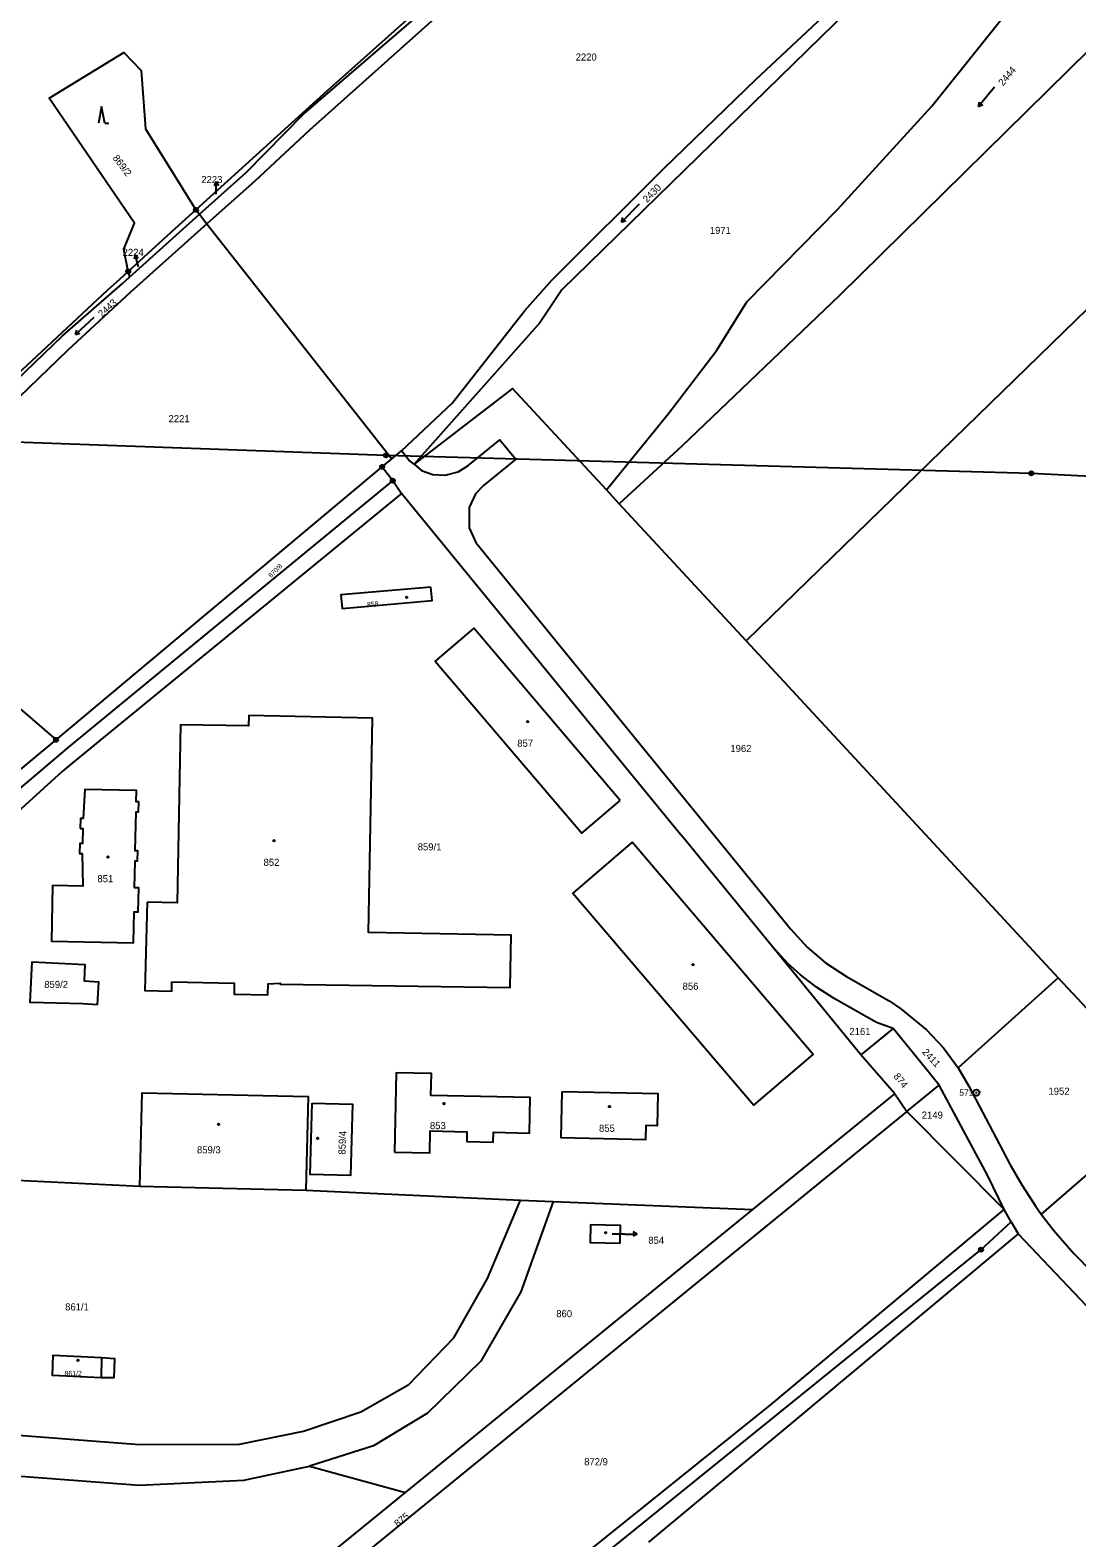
# Model space of a CAD drawing. Extents: x -504988 to -494607, y -1123820 to -1114018.
# Drawn here: x -502606.4 to -502355.4, y -1119993 to -1119631.6 of the extents above; entities that cross this region are included whole.
import ezdxf

# ---------------------------------------------------------------- set-up
doc = ezdxf.new("R2010")
doc.units = 0
for name, color, linetype in [('Hranice parcel', 7, 'Continuous'), ('Parcelní čísla', 7, 'Continuous'), ('Pop  PČ popisy', 7, 'Continuous'), ('Poz předměty', 7, 'Continuous'), ('Vnitřní kresba', 7, 'Continuous'), ('Značky bodu BP', 7, 'Continuous'), ('Značky budov', 7, 'Continuous'), ('Značky kultur', 7, 'Continuous')]:
    doc.layers.add(name, color=color, linetype=linetype)

msp = doc.modelspace()

# ---------------------------------------------------------------- linework, layer by layer
at = {"layer": 'Hranice parcel'}
for p, q in [((-502582.58, -1119690.79), (-502565.8, -1119675.75)), ((-502566.63, -1119674.69), (-502565.8, -1119675.75)), ((-502565.8, -1119675.75), (-502564, -1119678.03)), ((-502564, -1119678.03), (-502519.65, -1119734.37)), ((-502582.88, -1119689.44), (-502582.58, -1119690.79)), ((-502521.98, -1119736.27), (-502519.65, -1119734.37)), ((-502519.65, -1119734.37), (-502517.33, -1119732.48)), ((-502600.2, -1119801.7), (-502521.98, -1119736.27)), ((-502465.11, -1119745.14), (-502468.21, -1119741.8)), ((-502434.66, -1119778), (-502465.11, -1119745.14)), ((-502434.66, -1119778), (-502359.83, -1119858.73)), ((-502608.76, -1119794.28), (-502600.2, -1119801.7)), ((-502612.94, -1119812.35), (-502600.2, -1119801.7)), ((-502407.2, -1119877.25), (-502428.73, -1119850.93)), ((-502359.83, -1119858.73), (-502383.84, -1119880.37)), ((-502345.74, -1119873.93), (-502359.83, -1119858.73)), ((-502399.46, -1119870.92), (-502407.2, -1119877.25)), ((-502399.04, -1119886.56), (-502407.2, -1119877.25)), ((-502396.12, -1119890.8), (-502388.38, -1119884.46)), ((-502433.06, -1119914.26), (-502399.04, -1119886.56)), ((-502399.04, -1119886.56), (-502396.12, -1119890.8)), ((-502334.35, -1119889.76), (-502363.93, -1119915.42)), ((-502372.84, -1119914.3), (-502396.12, -1119890.8)), ((-502580.09, -1119908.69), (-502540.31, -1119909.68)), ((-502540.31, -1119909.68), (-502488.77, -1119912.04)), ((-502516.42, -1119982.14), (-502433.06, -1119914.26)), ((-502488.77, -1119912.04), (-502480.94, -1119912.35)), ((-502480.94, -1119912.35), (-502433.06, -1119914.26)), ((-502371.14, -1119917.24), (-502372.84, -1119914.3)), ((-502371.14, -1119917.24), (-502369.46, -1119920.13)), ((-502369.46, -1119920.13), (-502271.25, -1120023.8)), ((-502539.37, -1119975.81), (-502516.42, -1119982.14))]:
    msp.add_line(p, q, dxfattribs=at)
for points in [[(-502128.78, -1119382.75), (-502164.9, -1119386.2), (-502173.21, -1119390.26), (-502179.16, -1119399.85), (-502187, -1119431.57), (-502190.07, -1119444.01), (-502204.27, -1119473.56), (-502214.16, -1119489.36), (-502223.74, -1119506.4), (-502229.87, -1119513.8), (-502240.15, -1119526.05), (-502265.45, -1119550.93), (-502277.57, -1119560.18), (-502280.74, -1119562.7), (-502299.2, -1119571.51), (-502311.6, -1119583.47), (-502326.57, -1119605.06), (-502347.46, -1119631.46), (-502412.32, -1119695.22), (-502450.15, -1119731.29), (-502465.11, -1119745.14)], [(-502128.78, -1119382.75), (-502147.68, -1119459.24), (-502164.97, -1119495.21), (-502195.47, -1119542.5), (-502236.04, -1119584.84), (-502335.35, -1119681.42), (-502434.66, -1119778)], [(-502517.33, -1119732.48), (-502505.19, -1119721.04), (-502487.78, -1119698.79), (-502481.31, -1119691.51), (-502454.36, -1119664.71), (-502432.4, -1119643.44), (-502407.66, -1119620.25), (-502391.32, -1119604.16), (-502379, -1119591.92), (-502374.38, -1119584.08), (-502377.64, -1119576.05), (-502384.59, -1119563.69), (-502393.33, -1119552.76), (-502401.5, -1119542.45), (-502404.17, -1119542.98), (-502429.48, -1119562.95), (-502464.86, -1119592.04), (-502498.22, -1119618.75), (-502539.44, -1119655.59), (-502552.42, -1119667.72), (-502564, -1119678.03)], [(-502371.1, -1119588.68), (-502478.87, -1119693.82), (-502484.2, -1119701.73), (-502514.33, -1119735.66)], [(-502468.21, -1119741.8), (-502453.32, -1119723.48), (-502441.76, -1119708.31), (-502434.49, -1119696.75), (-502412.82, -1119674.63), (-502390.2, -1119649.83), (-502366.32, -1119620), (-502363.15, -1119610.6), (-502367.08, -1119594.08), (-502371.1, -1119588.68)], [(-502508.12, -1119622.05), (-502535.21, -1119646.18), (-502566.63, -1119674.69)], [(-502565.8, -1119675.75), (-502554.59, -1119665.71), (-502540.73, -1119651.67), (-502507.62, -1119623.08)], [(-502582.88, -1119689.44), (-502583.97, -1119684.1), (-502581.37, -1119677.85), (-502601.85, -1119647.92), (-502583.97, -1119636.95), (-502579.81, -1119641.28), (-502578.77, -1119655.23), (-502566.63, -1119674.69)], [(-502566.63, -1119674.69), (-502571.67, -1119679.26), (-502582.88, -1119689.44)], [(-502564, -1119678.03), (-502582.36, -1119694.39), (-502597.39, -1119708.35), (-502611.46, -1119721.88), (-502617.56, -1119736.16)], [(-502616.8, -1119729.06), (-502612.03, -1119717.7), (-502598.64, -1119704.84), (-502584.29, -1119692.32), (-502582.58, -1119690.79)], [(-502582.88, -1119689.44), (-502584.98, -1119691.35), (-502587.84, -1119693.94), (-502615.83, -1119719.98)], [(-502468.21, -1119741.8), (-502490.76, -1119717.47), (-502514.33, -1119735.66)], [(-502514.33, -1119735.66), (-502512.52, -1119737.15), (-502509.83, -1119738.12), (-502506.88, -1119738.28), (-502503.78, -1119737.48), (-502501.44, -1119736.03), (-502493.75, -1119729.77), (-502489.96, -1119734.42), (-502497.71, -1119740.73), (-502499.57, -1119742.72), (-502501.09, -1119746.01), (-502501.11, -1119750.87), (-502499.48, -1119754.38), (-502424.08, -1119847.02), (-502420.04, -1119851.43), (-502415.64, -1119855.17), (-502410.61, -1119858.46), (-502400.37, -1119864.31), (-502397.56, -1119866.17), (-502391.46, -1119871.2), (-502387.4, -1119875.56), (-502383.84, -1119880.37)], [(-502514.33, -1119735.66), (-502515.57, -1119734.64), (-502517.33, -1119732.48)], [(-502521.98, -1119736.27), (-502519.43, -1119739.59), (-502517.35, -1119742.66)], [(-502517.35, -1119742.66), (-502596.36, -1119807.31), (-502598.74, -1119809.28), (-502621.06, -1119829.53)], [(-502428.73, -1119850.93), (-502449.42, -1119825.64), (-502450.82, -1119823.93), (-502453.39, -1119820.8), (-502513.39, -1119747.48), (-502517.35, -1119742.66)], [(-502510.29, -1119765.08), (-502531.9, -1119766.98), (-502531.61, -1119770.26), (-502510, -1119768.35), (-502510.29, -1119765.08)], [(-502464.87, -1119816.24), (-502499.99, -1119774.98), (-502509.24, -1119782.85), (-502474.12, -1119824.1), (-502464.87, -1119816.24)], [(-502572.4, -1119859.76), (-502557.44, -1119860.04), (-502557.49, -1119862.68), (-502549.37, -1119862.84), (-502549.32, -1119860.23), (-502546.44, -1119860), (-502546.44, -1119860.29), (-502491.27, -1119861.04), (-502491.03, -1119848.55), (-502525.26, -1119847.9), (-502524.29, -1119796.49), (-502553.98, -1119795.92), (-502554.03, -1119798.38), (-502570.32, -1119798.08), (-502571.14, -1119840.77), (-502578.33, -1119840.66)], [(-502594.37, -1119822.97), (-502593.78, -1119822.99), (-502593.87, -1119826.57), (-502594.46, -1119826.55), (-502594.53, -1119828.96), (-502593.94, -1119828.98), (-502593.75, -1119836.77), (-502601.04, -1119836.62), (-502601.31, -1119849.96), (-502581.64, -1119850.36), (-502581.49, -1119842.94), (-502580.53, -1119842.96), (-502580.33, -1119837.19), (-502581.37, -1119837.17), (-502581.24, -1119830.74), (-502580.64, -1119830.75), (-502580.59, -1119828.32), (-502581.19, -1119828.31), (-502580.99, -1119819), (-502580.4, -1119819.01), (-502580.35, -1119816.6), (-502580.95, -1119816.59), (-502580.89, -1119813.89), (-502593.27, -1119813.64), (-502593.72, -1119820.56), (-502594.31, -1119820.54), (-502594.37, -1119822.97)], [(-502462, -1119826.27), (-502476.24, -1119838.43), (-502432.84, -1119889.29), (-502418.59, -1119877.13), (-502462, -1119826.27)], [(-502621.06, -1119829.53), (-502622.79, -1119906.64), (-502580.09, -1119908.69)], [(-502578.33, -1119840.66), (-502578.87, -1119861.77), (-502572.46, -1119861.92), (-502572.4, -1119859.76)], [(-502399.46, -1119870.92), (-502403.4, -1119869.45), (-502413.57, -1119863.68), (-502417.84, -1119860.99), (-502421.65, -1119858.06), (-502424.68, -1119855.29), (-502428.73, -1119850.93)], [(-502590.32, -1119865.2), (-502593.76, -1119865.03), (-502606.37, -1119864.7), (-502605.95, -1119854.92), (-502593.26, -1119855.53), (-502593.45, -1119859.51), (-502590.01, -1119859.69), (-502590.32, -1119865.2)], [(-502388.38, -1119884.46), (-502391.79, -1119880.3), (-502399.46, -1119870.92)], [(-502519.03, -1119900.55), (-502510.57, -1119900.73), (-502510.46, -1119895.47), (-502501.64, -1119895.66), (-502501.7, -1119898.03), (-502495.36, -1119898.17), (-502495.31, -1119895.79), (-502486.68, -1119895.98), (-502486.5, -1119887.46), (-502510.28, -1119886.94), (-502510.16, -1119881.73), (-502518.61, -1119881.54), (-502519.03, -1119900.55)], [(-502383.84, -1119880.37), (-502381.27, -1119884.73), (-502371.42, -1119903.42), (-502368.61, -1119908.39), (-502365.24, -1119913.58), (-502363.93, -1119915.42)], [(-502580.09, -1119908.69), (-502579.57, -1119886.33), (-502539.73, -1119887.19), (-502540.31, -1119909.68)], [(-502478.87, -1119886.1), (-502479.1, -1119897.06), (-502458.74, -1119897.49), (-502458.67, -1119894.08), (-502455.96, -1119894.14), (-502455.8, -1119886.58), (-502478.87, -1119886.1)], [(-502372.84, -1119914.3), (-502376.73, -1119906.22), (-502388.38, -1119884.46)], [(-502538.74, -1119888.77), (-502529.12, -1119889.02), (-502529.58, -1119906.12), (-502539.22, -1119905.9), (-502538.74, -1119888.77)], [(-502396.12, -1119890.8), (-502566.84, -1120029.94), (-502587.36, -1120052.45), (-502608.42, -1120076.47), (-502633.38, -1120096.81)], [(-502701.82, -1119961), (-502680.9, -1119959.47), (-502648.34, -1119962.6), (-502617.61, -1119967.74), (-502580.14, -1119970.61), (-502556.23, -1119970.53), (-502540.81, -1119967.45), (-502527.06, -1119962.76), (-502515.62, -1119956.25), (-502504.82, -1119945.07), (-502496.7, -1119930.81), (-502488.77, -1119912.04)], [(-502539.17, -1120129.38), (-502550.09, -1120101.33), (-502565.41, -1120066.4), (-502556.62, -1120058.59), (-502542.2, -1120052.17), (-502428.59, -1119960.97), (-502372.84, -1119914.3)], [(-502480.94, -1119912.35), (-502488.75, -1119934), (-502498.32, -1119950.65), (-502511.11, -1119963.08), (-502524.08, -1119970.96), (-502539.37, -1119975.81)], [(-502510.03, -1120162.22), (-502522.53, -1120148.04), (-502540.02, -1120119.07), (-502555.09, -1120082.05), (-502553.66, -1120072.7), (-502545.55, -1120063.24), (-502488.39, -1120012.91), (-502378.38, -1119923.93), (-502371.14, -1119917.24)], [(-502464.91, -1119922.34), (-502464.82, -1119918.15), (-502471.99, -1119918), (-502472.07, -1119922.19), (-502464.91, -1119922.34)], [(-502363.93, -1119915.42), (-502360.92, -1119919.32), (-502356.11, -1119924.82), (-502271.75, -1120010.63), (-502258.23, -1120024.92), (-502255.98, -1120027.81), (-502253.76, -1120034.16), (-502254.99, -1120043.43), (-502256.73, -1120046.58), (-502346.48, -1120124.79), (-502436.23, -1120202.99)], [(-502369.46, -1119920.13), (-502423.33, -1119965.12), (-502458.12, -1119994.04)], [(-502589.31, -1119949.73), (-502586.18, -1119950.02), (-502586.33, -1119954.61), (-502589.36, -1119954.61), (-502601.08, -1119954.06), (-502600.85, -1119949.2), (-502589.31, -1119949.73)], [(-502701.9, -1119970.8), (-502681.57, -1119972.49), (-502648.5, -1119972.28), (-502619.23, -1119977.45), (-502580.24, -1119980.39), (-502555.18, -1119979.17), (-502539.37, -1119975.81)], [(-502591.59, -1120050.18), (-502570.78, -1120026.41), (-502516.42, -1119982.14)]]:
    msp.add_lwpolyline(points, dxfattribs=at)
at = {"layer": 'Pop  PČ popisy'}
for p, q in [((-502561.76, -1119667.9), (-502562.26, -1119668.9)), ((-502561.76, -1119670.9), (-502561.76, -1119667.9)), ((-502561.76, -1119667.9), (-502561.26, -1119668.9)), ((-502581.23, -1119685.4), (-502581.45, -1119686.5)), ((-502580.45, -1119688.3), (-502581.23, -1119685.4)), ((-502581.23, -1119685.4), (-502580.48, -1119686.24)), ((-502463.8, -1119920.17), (-502466.8, -1119920.17)), ((-502463.8, -1119920.17), (-502460.8, -1119920.17)), ((-502460.8, -1119920.17), (-502461.8, -1119919.67)), ((-502460.8, -1119920.17), (-502461.8, -1119920.67))]:
    msp.add_line(p, q, dxfattribs=at)
at = {"layer": 'Poz předměty'}
for p, q in [((-502656.18, -1119728.63), (-502521.05, -1119733.51)), ((-502521.05, -1119733.51), (-502366.32, -1119737.83)), ((-502366.32, -1119737.83), (-502184.57, -1119746.9))]:
    msp.add_line(p, q, dxfattribs=at)
for centre, radius in [((-502521.05, -1119733.51), 0.5), ((-502521.05, -1119733.51), 0.4), ((-502521.05, -1119733.51), 0.3), ((-502521.05, -1119733.51), 0.2), ((-502521.05, -1119733.51), 0.1), ((-502366.32, -1119737.83), 0.5), ((-502366.32, -1119737.83), 0.4), ((-502366.32, -1119737.83), 0.3), ((-502366.32, -1119737.83), 0.2), ((-502366.32, -1119737.83), 0.1)]:
    msp.add_circle(centre, radius, dxfattribs=at)
at = {"layer": 'Vnitřní kresba'}
for p, q in [((-502519.43, -1119739.59), (-502597.5, -1119803.74)), ((-502597.5, -1119803.74), (-502632.3, -1119833.14)), ((-502589.31, -1119949.73), (-502589.36, -1119954.61))]:
    msp.add_line(p, q, dxfattribs=at)
at = {"layer": 'Značky bodu BP'}
for centre, radius in [((-502566.63, -1119674.69), 0.5), ((-502566.63, -1119674.69), 0.0303), ((-502582.88, -1119689.44), 0.5), ((-502582.88, -1119689.44), 0.0303), ((-502521.98, -1119736.27), 0.5), ((-502521.98, -1119736.27), 0.0303), ((-502519.43, -1119739.59), 0.5), ((-502519.43, -1119739.59), 0.0303), ((-502600.2, -1119801.7), 0.5), ((-502600.2, -1119801.7), 0.0303), ((-502379.47, -1119886.27), 0.75), ((-502379.47, -1119886.27), 0.03), ((-502378.38, -1119923.93), 0.5), ((-502378.38, -1119923.93), 0.0303)]:
    msp.add_circle(centre, radius, dxfattribs=at)
at = {"layer": 'Značky budov'}
for centre in [(-502516.07, -1119767.55), (-502487.06, -1119797.33), (-502547.92, -1119825.87), (-502587.75, -1119829.79), (-502447.42, -1119855.58), (-502507.16, -1119888.93), (-502467.46, -1119889.62), (-502561.21, -1119893.89), (-502537.46, -1119897.23), (-502468.36, -1119919.87), (-502594.95, -1119950.44)]:
    msp.add_circle(centre, 0.175, dxfattribs=at)
at = {"layer": 'Značky kultur'}
for p, q in [((-502375.13, -1119645.28), (-502378.99, -1119649.88)), ((-502589.28, -1119649.9), (-502590.03, -1119653.9)), ((-502588.53, -1119653.9), (-502589.28, -1119649.9)), ((-502378.99, -1119649.88), (-502378.74, -1119648.8)), ((-502378.99, -1119649.88), (-502377.97, -1119649.45)), ((-502588.53, -1119653.9), (-502587.53, -1119653.9)), ((-502460.38, -1119673.28), (-502464.55, -1119677.59)), ((-502464.55, -1119677.59), (-502464.23, -1119676.54)), ((-502464.55, -1119677.59), (-502463.51, -1119677.24)), ((-502591.1, -1119700.52), (-502595.56, -1119704.53)), ((-502595.56, -1119704.53), (-502595.17, -1119703.51)), ((-502595.56, -1119704.53), (-502594.5, -1119704.25))]:
    msp.add_line(p, q, dxfattribs=at)

# ---------------------------------------------------------------- texts
at = {"layer": 'Parcelní čísla'}
for s, height, p in [('2220', 1.7, (-502475.58, -1119638.9)), ('2223', 1.7, (-502565.36, -1119668.26)), ('1971', 1.7, (-502443.41, -1119680.45)), ('2224', 1.7, (-502584.22, -1119685.72)), ('2221', 1.7, (-502573.21, -1119725.58)), ('857', 1.7, (-502489.58, -1119803.38)), ('1962', 1.7, (-502438.48, -1119804.63)), ('859/1', 1.7, (-502513.46, -1119828.22)), ('852', 1.7, (-502550.43, -1119831.92)), ('851', 1.7, (-502590.27, -1119835.84)), ('859/2', 1.7, (-502603.02, -1119861.19)), ('856', 1.7, (-502449.93, -1119861.63)), ('2161', 1.7, (-502409.92, -1119872.46)), ('1952', 1.7, (-502362.19, -1119886.79)), ('853', 1.7, (-502510.53, -1119895.03)), ('2149', 1.7, (-502392.58, -1119892.51)), ('855', 1.7, (-502469.98, -1119895.67)), ('859/3', 1.7, (-502566.39, -1119900.83)), ('854', 1.7, (-502458.15, -1119922.52)), ('861/1', 1.7, (-502598.01, -1119938.48)), ('860', 1.7, (-502480.23, -1119940.11)), ('861/2', 1.2, (-502598.16, -1119954.17)), ('872/9', 1.7, (-502473.53, -1119975.6))]:
    msp.add_text(s, height=height, dxfattribs=at).set_placement(p)
for s, height, rotation, p in [('2444', 1.7, 50, (-502373.08, -1119645.09)), ('869/2', 1.7, 307, (-502586.7, -1119662.27)), ('2430', 1.7, 45, (-502458.48, -1119673.08)), ('2443', 1.7, 42, (-502589.18, -1119700.53)), ('870/8', 1.139, 45, (-502548.62, -1119762.96)), ('858', 1.2, 4, (-502525.57, -1119769.89)), ('2411', 1.7, 313, (-502392.61, -1119876.67)), ('874', 1.7, 309, (-502399.47, -1119882.42)), ('859/4', 1.7, 88, (-502530.79, -1119901.15)), ('875', 1.7, 39, (-502518.24, -1119990.49))]:
    msp.add_text(s, height=height, rotation=rotation, dxfattribs=at).set_placement(p)
at = {"layer": 'Značky bodu BP'}
msp.add_text('571', height=1.5, dxfattribs=at).set_placement((-502383.57, -1119887.02))

doc.saveas('drawing.dxf')
